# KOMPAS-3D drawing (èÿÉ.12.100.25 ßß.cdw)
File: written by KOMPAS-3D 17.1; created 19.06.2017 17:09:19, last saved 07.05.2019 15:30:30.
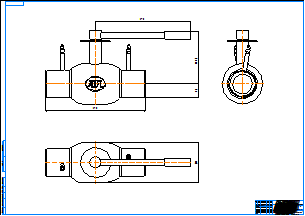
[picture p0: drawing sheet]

Sheet 1: A0, landscape

Title block, sheet 1: name: КШР.12.100.25 сс; material: Внимание! Данный продукт является объектом авторского права ООО «Торговый Дом АДЛ». / Запрещается изменение, копирование, распространение / (в том числе путем копирования на другие сайты и ресурсы в Интернете) / или любое иное использование информации и объектов без предварительного / согласия правообладателя (ООО «Торговый Дом АДЛ»).; scale: 1:1; sheets: 1; organisation: ООО "Торговый дом АДЛ"; sheet format: A0; stored path: C:\Users\tra\Desktop\2д чертежи\Шаровые краны БИВАЛ\КШР_Бивал_серия_12\KOMPAS 2D\КШР.12.100.25 сс.cdw

Views: Спереди 1, Проекционный вид 2, Проекционный вид 3
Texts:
  Klimkovich
  ADL
Dimensions and other numbers on the sheet: 390; 370; 205,1; 54; 159; 1:1; 1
